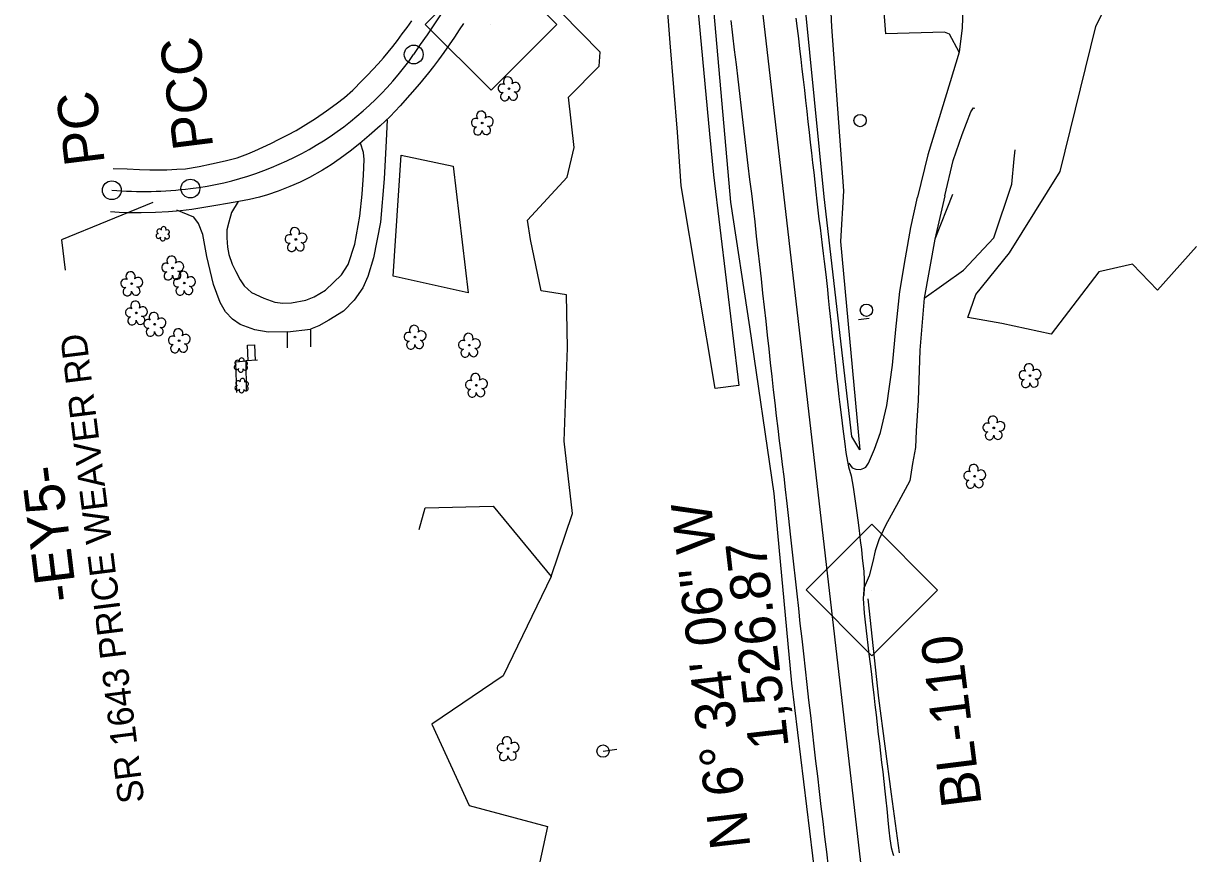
# Model space of a CAD drawing. Extents: x 476627 to 479509, y 495837 to 499842.
# Drawn here: x 477859.6 to 478327.6, y 496914.6 to 497245.6 of the extents above; entities that cross this region are included whole.
import ezdxf

# ---------------------------------------------------------------- set-up
doc = ezdxf.new("R2010")
doc.units = 0
for name, color, linetype in [('CTL Secondary Horizontal and Vertical CELL', 7, 'Continuous'), ('CTL Secondary Horizontal and Vertical Text', 7, 'Continuous'), ('Exist Guardrail', 7, 'Continuous'), ('Exist Horizontal Alignment', 7, 'Continuous'), ('Exist Horizontal Alignment Direction Label', 7, 'Continuous'), ('Exist Other Culture Area Outline', 7, 'Continuous'), ('Exist Other Culture Sign', 7, 'Continuous'), ('Exist Roads EOP', 7, 'Continuous'), ('Exist Roads EOP Leader', 7, 'Continuous'), ('Exist Roads EOP Other', 7, 'Continuous'), ('Exist Roads EOP Text', 7, 'Continuous'), ('Exist Roads Soil', 7, 'Continuous'), ('Exist Utilities Other Pole CELL', 7, 'Continuous'), ('Exist Utilities Power Pole CELL', 7, 'Continuous'), ('Exist Vegetation Hedge Row', 7, 'Continuous'), ('Exist Vegetation Shrub CELL', 7, 'Continuous'), ('Exist Vegetation Tree CELL', 7, 'Continuous'), ('Exist Vegetation Woods Line', 7, 'Continuous')]:
    doc.layers.add(name, color=color, linetype=linetype)

msp = doc.modelspace()

# ---------------------------------------------------------------- linework, layer by layer
at = {"layer": 'CTL Secondary Horizontal and Vertical CELL'}
for p, q in [((478046.04, 497245.12), (478046.04, 497245.12)), ((478197.94, 497019.66), (478197.94, 497019.66))]:
    msp.add_line(p, q, dxfattribs=at)
for points in [[(478019.96, 497245.21), (478046.17, 497271.41), (478072.42, 497245.16), (478046.21, 497218.96)], [(478171.87, 497019.75), (478198.07, 497045.96), (478224.32, 497019.7), (478198.12, 496993.5)]]:
    msp.add_lwpolyline(points, close=True, dxfattribs=at)
at = {"layer": 'Exist Guardrail'}
msp.add_lwpolyline([(478196.51, 497016.23), (478200.72, 496976.63), (478205.75, 496938.31), (478209.04, 496914.92)], dxfattribs=at)
at = {"layer": 'Exist Horizontal Alignment'}
msp.add_line((478241.22, 496498.17), (478119.71, 497553.37), dxfattribs=at)
for centre in [(478015.32, 497233.23), (477894.89, 497179.1), (477926.23, 497179.77)]:
    msp.add_circle(centre, 3.75, dxfattribs=at)
for centre, radius, start, end in [((477193.06, 497809.1), 1003.86, 324.99436, 333.75894), ((477910.8, 497306.43), 127.59, 276.944, 324.9944), ((477907.25, 497335.63), 157.01, 265.4855, 276.944)]:
    msp.add_arc(centre, radius, start, end, dxfattribs=at)
at = {"layer": 'Exist Other Culture Area Outline'}
msp.add_line((477944.56, 497110.62), (477948.31, 497111.05), dxfattribs=at)
for points in [[(477965.02, 497116.32), (477964.93, 497122.58), (477974.09, 497123.73), (477974.12, 497116.68)], [(477949.32, 497111.1), (477949.07, 497117.32), (477951.81, 497117.4), (477952.11, 497111.24)], [(477944.77, 497098.47), (477944.41, 497110.43)], [(477952.99, 497111.28), (477948.31, 497111.05), (477948.54, 497099.08)]]:
    msp.add_lwpolyline(points, dxfattribs=at)
at = {"layer": 'Exist Other Culture Sign'}
msp.add_line((478197.08, 497127.9), (478192.79, 497127.43), dxfattribs=at)
at = {"layer": 'Exist Roads EOP'}
for points in [[(478035.23, 497245.64), (478033.52, 497243.02), (478031.58, 497240.11), (478029.48, 497237.05), (478027.33, 497234), (478025.21, 497231.08), (478023.21, 497228.41), (478021.29, 497225.96), (478017.62, 497221.51), (478013.84, 497217.13), (478009.92, 497212.8), (478005.91, 497208.5), (478001.95, 497204.74), (477997.62, 497200.92), (477993.83, 497197.76), (477990.02, 497194.74), (477986.02, 497191.78), (477982.41, 497189.27), (477978.98, 497187.06), (477973.75, 497184.13), (477970.07, 497182.34), (477965.93, 497180.53), (477961.26, 497178.77), (477956.98, 497177.28), (477953.76, 497176.28), (477949.79, 497175.4), (477945.54, 497174.58), (477941.05, 497173.77), (477936.39, 497172.96), (477931.62, 497172.16), (477926.85, 497171.47), (477922.23, 497170.93), (477917.5, 497170.5), (477912.35, 497170.25), (477906.55, 497170.12), (477900.71, 497170.14), (477897.87, 497170.26), (477894.37, 497170.45)], [(477895.41, 497187.76), (477901.06, 497187.58), (477905.9, 497187.4), (477910.04, 497187.25), (477914.56, 497187.23), (477916.83, 497187.29), (477920.82, 497187.44), (477924.23, 497187.69), (477929.69, 497188.59), (477934.63, 497189.6), (477940.1, 497190.77), (477944.94, 497192.07), (477949.09, 497193.64), (477951.93, 497194.83), (477955.14, 497196.25), (477958.39, 497197.78), (477961.71, 497199.43), (477965.14, 497201.2), (477968.41, 497202.96), (477971.29, 497204.61), (477976.2, 497207.7), (477980.57, 497210.73), (477984.35, 497213.49), (477987.66, 497216.06), (477991.07, 497219.04), (477994.8, 497222.81), (477996.85, 497224.96), (477999, 497227.24), (478001.16, 497229.56), (478003.21, 497231.86), (478006.98, 497236.47), (478008.81, 497238.87), (478010.74, 497241.4), (478012.69, 497244.02), (478014.57, 497246.71)], [(478180.78, 496909.15), (478180.07, 496915.25), (478179.35, 496921.32), (478178.62, 496927.36), (478177.9, 496933.39), (478177.18, 496939.41), (478176.48, 496945.43), (478175.79, 496951.44), (478175.1, 496957.47), (478174.41, 496963.55), (478173.71, 496969.66), (478173.01, 496975.82), (478172.31, 496981.97), (478171.62, 496988.1), (478170.93, 496994.2), (478170.24, 497000.26), (478169.56, 497006.29), (478168.9, 497012.27), (478168.25, 497018.21), (478167.62, 497024.1), (478166.99, 497030), (478166.34, 497035.98), (478165.68, 497042.03), (478164.99, 497048.16), (478164.32, 497054.13), (478163.67, 497059.72), (478163.06, 497064.92), (478162.47, 497069.73), (478161.9, 497074.41), (478161.31, 497079.21), (478160.71, 497084.14), (478160.1, 497089.18), (478159.48, 497094.33), (478158.88, 497099.57), (478158.27, 497104.89), (478157.68, 497110.31), (478157.08, 497115.8), (478156.48, 497121.32), (478155.87, 497126.88), (478155.25, 497132.48), (478154.63, 497138.12), (478154.01, 497143.77), (478153.39, 497149.44), (478152.77, 497155.13), (478152.14, 497160.82), (478151.49, 497166.49), (478150.83, 497172.13), (478150.16, 497177.75), (478149.48, 497183.37), (478148.8, 497189.01), (478148.13, 497194.68), (478147.46, 497200.37), (478146.78, 497206.08), (478146.11, 497211.83), (478145.42, 497217.61), (478144.73, 497223.41), (478144.04, 497229.25), (478143.35, 497235.1), (478142.67, 497240.96), (478141.99, 497246.84)], [(478167.81, 497247.69), (478168.29, 497243.63), (478168.77, 497239.56), (478169.25, 497235.49), (478169.73, 497231.42), (478170.21, 497227.33), (478170.68, 497223.2), (478171.16, 497219.03), (478171.64, 497214.83), (478172.11, 497210.61), (478172.59, 497206.43), (478173.06, 497202.27), (478173.53, 497198.14), (478174, 497194.07), (478174.45, 497190.06), (478174.9, 497186.14), (478175.33, 497182.29), (478175.76, 497178.51), (478176.18, 497174.79), (478176.59, 497171.15), (478177, 497167.58), (478177.41, 497164.06), (478177.81, 497160.61), (478178.22, 497157.22), (478178.64, 497153.89), (478179.03, 497150.75), (478179.69, 497145.44), (478180.38, 497139.5), (478180.72, 497136.18), (478181.11, 497132.23), (478181.69, 497126.55), (478182.27, 497120.93), (478182.86, 497115.31), (478183.15, 497112.68), (478183.54, 497109.26), (478184.03, 497105.05), (478184.53, 497100.71), (478184.97, 497096.91), (478185.35, 497093.64), (478185.96, 497088.51), (478186.49, 497084.01), (478186.75, 497081.91), (478187.25, 497078.03), (478187.74, 497074.55), (478188.79, 497068.84), (478189.78, 497065.24), (478190.68, 497060.69), (478191.49, 497055.11), (478191.97, 497051.45), (478192.48, 497047.49), (478192.99, 497043.43), (478193.48, 497039.5), (478193.92, 497035.81), (478194.29, 497032.47), (478194.84, 497027.03), (478195.09, 497023.7), (478195.09, 497021.63), (478194.65, 497016.28), (478195.04, 497010.48), (478195.43, 497006.88), (478196.1, 497001.22), (478196.51, 496997.77), (478196.95, 496994.1), (478197.41, 496990.22), (478197.9, 496986.12), (478198.39, 496981.96), (478198.86, 496977.88), (478199.33, 496973.88), (478199.78, 496969.96), (478200.22, 496966.1), (478200.67, 496962.28), (478201.11, 496958.48), (478201.56, 496954.71), (478202, 496950.95), (478202.43, 496947.17), (478202.85, 496943.37), (478203.27, 496939.54), (478203.66, 496935.85), (478204.02, 496932.44), (478204.66, 496926.48), (478204.92, 496924.01), (478205.32, 496920.44), (478205.85, 496916.99), (478206.46, 496914.68), (478206.77, 496913.89)]]:
    msp.add_lwpolyline(points, dxfattribs=at)
at = {"layer": 'Exist Roads EOP Leader'}
msp.add_lwpolyline([(477911.24, 497174.19), (477874.76, 497159.27), (477876.27, 497147.26)], dxfattribs=at)
at = {"layer": 'Exist Roads EOP Other'}
for points in [[(478234.58, 497255.76), (478234.09, 497243.91), (478232.9, 497234.19), (478229.32, 497222.36), (478224.43, 497206.22), (478220.47, 497193.22), (478216.26, 497176.28)], [(478227.18, 497176.89), (478230.49, 497190.94), (478234.13, 497201.38), (478237.6, 497210.3), (478238.69, 497211.92), (478239.15, 497211.85)], [(478188.86, 497070.34), (478190.3, 497068.4), (478191.74, 497067.91), (478193.58, 497067.8), (478194.87, 497068.33), (478195.63, 497068.74), (478196.75, 497070.24), (478199.13, 497075.89), (478201.53, 497082.51), (478204.12, 497093.25), (478206.39, 497109.37), (478207.68, 497123.62), (478209.32, 497138.79), (478211.55, 497152.2), (478213.68, 497164.25), (478216.26, 497176.28)], [(478227.18, 497176.89), (478223.23, 497159.59), (478218.95, 497136.12), (478217.23, 497115.29), (478216.54, 497095.28), (478215.82, 497083.22), (478215.49, 497076.53), (478214.32, 497070.17), (478213.3, 497063.29), (478208.75, 497054.86), (478203.56, 497045.36), (478200.94, 497039.69), (478199.44, 497035.36), (478198.53, 497031.09), (478196.97, 497025.37), (478194.98, 497020.7), (478194.83, 497017.55)]]:
    msp.add_lwpolyline(points, dxfattribs=at)
at = {"layer": 'Exist Roads Soil'}
for points in [[(478232.9, 497234.19), (478229.08, 497241.38), (478227.08, 497242.13), (478203.69, 497241.5), (478202.19, 497260.65), (478201.46, 497277.13), (478202.27, 497279.15), (478209.18, 497280.95), (478211.76, 497282.22), (478214.52, 497285.39)], [(478004.71, 497207.12), (478004.35, 497198.84), (478003.51, 497183.67), (478002.14, 497166.34), (477999.29, 497152.11), (477997.02, 497144.74), (477995.02, 497140.13), (477991.61, 497135.24), (477987.33, 497130.92), (477981.46, 497127.24), (477977.53, 497125.03), (477974.09, 497123.73)], [(477945.27, 497174.56), (477942.68, 497170.16), (477941.54, 497166.42), (477940.81, 497163.32), (477940.75, 497160.15), (477941.04, 497156.46), (477941.53, 497153.51), (477942.85, 497149.68), (477944.3, 497146.72), (477946.06, 497143.35), (477947.71, 497141.01), (477950.56, 497138.38), (477955.52, 497136.01), (477959.97, 497134.48), (477963.16, 497134.04), (477966.63, 497134.25), (477972.23, 497135.26), (477975.67, 497136.58), (477980.1, 497139.29), (477986.52, 497145.4), (477989.14, 497149.51), (477991.9, 497157.65), (477993.79, 497168.7), (477994.81, 497177.54), (477995.32, 497185.1), (477995.51, 497191.42), (477995.23, 497194.09), (477994.09, 497197.93)], [(478218.95, 497136.12), (478234.59, 497147.19), (478246.82, 497160.07), (478253.98, 497181.47), (478254.93, 497191.6), (478255.23, 497195.18)], [(478230.22, 497177.39), (478223.23, 497159.59)], [(477964.93, 497122.58), (477957.24, 497122.47), (477951.92, 497123.44), (477946.12, 497125.54), (477942.97, 497127.71), (477940.2, 497130.65), (477938.14, 497134.34), (477935.52, 497141.52), (477932.84, 497152.72), (477931.21, 497161.46), (477929.45, 497165.82), (477927.64, 497168.34), (477920.89, 497171.21)]]:
    msp.add_lwpolyline(points, dxfattribs=at)
at = {"layer": 'Exist Utilities Other Pole CELL'}
for centre in [(478193.42, 497206.9), (478195.91, 497131.26)]:
    msp.add_circle(centre, 2.46, dxfattribs=at)
at = {"layer": 'Exist Utilities Power Pole CELL'}
for q in [(478096.41, 496956.24), (478090.84, 496955.47)]:
    msp.add_line((478090.84, 496955.47), q, dxfattribs=at)
msp.add_circle((478090.84, 496955.47), 2.45, dxfattribs=at)
at = {"layer": 'Exist Vegetation Hedge Row'}
for points in [[(478190.09, 497080.94), (478179.04, 497176.49), (478167.62, 497291.69), (478149.68, 497459.52), (478153.94, 497461.52), (478164.92, 497407.53), (478169.64, 497380.94), (478176.79, 497323.8), (478179.27, 497301.23), (478182, 497244.2), (478186.73, 497178.82), (478185.59, 497158.67), (478193.35, 497075.53), (478190.09, 497080.94)], [(478061.9, 497159.5), (478060.76, 497167.21), (478076.59, 497184.26), (478079.28, 497196.19), (478077.12, 497216.22), (478089.28, 497228.61), (478089.68, 497234.1), (478074.26, 497249.81), (478051.02, 497260.79), (478081, 497317.4), (478090.81, 497331.53), (478107.74, 497357.73), (478122.56, 497359.77), (478132.29, 497281.51), (478141.65, 497174.35)], [(478141.65, 497174.35), (478149.25, 497124.62), (478158.96, 497058.2), (478166.01, 496982.58), (478178.06, 496884.14), (478154.97, 496858.56), (478116.58, 496816.35), (478093.34, 496801.61), (478073.88, 496796.87), (478056.27, 496795.04), (478052.86, 496799.11), (478045.86, 496797.88)], [(478070.12, 497025.14), (478078.66, 497050.24), (478075.36, 497079.1), (478076.69, 497116.32), (478076.31, 497137.46), (478066.2, 497139.04), (478061.9, 497159.5)]]:
    msp.add_lwpolyline(points, dxfattribs=at)
at = {"layer": 'Exist Vegetation Shrub CELL'}
for p, q in [((477915.3, 497161.55), (477915.3, 497161.55)), ((477946.44, 497109.19), (477946.44, 497109.19)), ((477946.77, 497101.02), (477946.77, 497101.02))]:
    msp.add_line(p, q, dxfattribs=at)
for centre, radius, start, end in [((477915.53, 497163.59), 0.99, 334.8391, 200.4717), ((477913.5, 497160.85), 0.955, 95.1099, 327.9534), ((477913.82, 497162.68), 0.968, 35.8908, 245.4216), ((477915.18, 497159.87), 0.984, 151.2797, 21.387), ((477916.94, 497160.62), 0.937, 204.9913, 73.4601), ((477916.98, 497162.42), 0.929, 284.4567, 126.0861), ((477944.64, 497108.49), 0.955, 95.1099, 327.9534), ((477944.96, 497110.32), 0.968, 35.8908, 245.4216), ((477946.31, 497107.51), 0.984, 151.2797, 21.387), ((477946.67, 497111.23), 0.99, 334.8391, 200.4717), ((477948.08, 497108.27), 0.937, 204.9913, 73.4601), ((477948.11, 497110.06), 0.929, 284.4567, 126.0861), ((477945.29, 497102.14), 0.968, 35.8908, 245.4216), ((477947, 497103.06), 0.99, 334.8391, 200.4717), ((477944.97, 497100.31), 0.955, 95.1099, 327.9534), ((477946.64, 497099.33), 0.984, 151.2797, 21.387), ((477948.41, 497100.09), 0.937, 204.9913, 73.4601), ((477948.44, 497101.88), 0.929, 284.4567, 126.0861)]:
    msp.add_arc(centre, radius, start, end, dxfattribs=at)
at = {"layer": 'Exist Vegetation Tree CELL'}
for p, q in [((478053.33, 497219.58), (478053.33, 497219.58)), ((478042.64, 497205.91), (478042.64, 497205.91)), ((477968.33, 497159.49), (477968.33, 497159.49)), ((477919.12, 497148.13), (477919.12, 497148.13)), ((477902.79, 497141.84), (477902.79, 497141.84)), ((477923.82, 497142.08), (477923.82, 497142.08)), ((477904.67, 497130.19), (477904.67, 497130.19)), ((477912.01, 497125.67), (477912.01, 497125.67)), ((477921.75, 497119.12), (477921.75, 497119.12)), ((478015.85, 497120.53), (478015.85, 497120.53)), ((478037.53, 497117.33), (478037.53, 497117.33)), ((478261.15, 497105.21), (478261.15, 497105.21)), ((478040.32, 497101.36), (478040.32, 497101.36)), ((478246.73, 497084.35), (478246.73, 497084.35)), ((478239.11, 497065.08), (478239.11, 497065.08)), ((478052.91, 496956.48), (478052.91, 496956.48))]:
    msp.add_line(p, q, dxfattribs=at)
for centre in [(478053.33, 497219.58), (478042.64, 497205.91), (477968.33, 497159.49), (477919.12, 497148.13), (477902.79, 497141.84), (477923.82, 497142.08), (477904.67, 497130.19), (477912.01, 497125.67), (477921.75, 497119.12), (478015.85, 497120.53), (478037.53, 497117.33), (478261.15, 497105.21), (478040.32, 497101.36), (478246.73, 497084.35), (478239.11, 497065.08), (478052.91, 496956.48)]:
    msp.add_circle(centre, 0.326, dxfattribs=at)
for centre, radius, start, end in [((478050.72, 497219.73), 1.73, 62.6636, 279.3457), ((478052.94, 497222.45), 1.86, 330.1651, 219.7134), ((478055.87, 497220.17), 1.9, 257.1011, 134.1999), ((478051.62, 497216.46), 1.69, 111.5671, 6.231), ((478055, 497216.68), 1.7, 181.2822, 74.56), ((478042.25, 497208.78), 1.86, 330.1651, 219.7134), ((478040.03, 497206.06), 1.73, 62.6636, 279.3457), ((478045.19, 497206.5), 1.9, 257.1011, 134.1999), ((478040.93, 497202.79), 1.69, 111.5671, 6.231), ((478044.31, 497203.01), 1.7, 181.2822, 74.56), ((477967.94, 497162.37), 1.86, 330.1651, 219.7134), ((477965.72, 497159.65), 1.73, 62.6636, 279.3457), ((477970.88, 497160.08), 1.9, 257.1011, 134.1999), ((477966.62, 497156.37), 1.69, 111.5671, 6.231), ((477970, 497156.59), 1.7, 181.2822, 74.56), ((477916.51, 497148.28), 1.73, 62.6636, 279.3457), ((477918.73, 497151), 1.86, 330.1651, 219.7134), ((477921.67, 497148.71), 1.9, 257.1011, 134.1999), ((477902.4, 497144.71), 1.86, 330.1651, 219.7134), ((477917.41, 497145.01), 1.69, 111.5671, 6.231), ((477920.79, 497145.23), 1.7, 181.2822, 74.56), ((477923.44, 497144.95), 1.86, 330.1651, 219.7134), ((477900.18, 497141.99), 1.73, 62.6636, 279.3457), ((477904.46, 497138.94), 1.7, 181.2822, 74.56), ((477905.33, 497142.43), 1.9, 257.1011, 134.1999), ((477921.22, 497142.23), 1.73, 62.6636, 279.3457), ((477922.12, 497138.96), 1.69, 111.5671, 6.231), ((477925.49, 497139.18), 1.7, 181.2822, 74.56), ((477926.37, 497142.67), 1.9, 257.1011, 134.1999), ((477901.08, 497138.72), 1.69, 111.5671, 6.231), ((477902.06, 497130.34), 1.73, 62.6636, 279.3457), ((477904.28, 497133.06), 1.86, 330.1651, 219.7134), ((477907.22, 497130.78), 1.9, 257.1011, 134.1999), ((477902.96, 497127.07), 1.69, 111.5671, 6.231), ((477906.34, 497127.29), 1.7, 181.2822, 74.56), ((477909.4, 497125.82), 1.73, 62.6636, 279.3457), ((477911.62, 497128.54), 1.86, 330.1651, 219.7134), ((477914.56, 497126.26), 1.9, 257.1011, 134.1999), ((477910.3, 497122.55), 1.69, 111.5671, 6.231), ((477913.68, 497122.77), 1.7, 181.2822, 74.56), ((477921.37, 497121.99), 1.86, 330.1651, 219.7134), ((478013.25, 497120.69), 1.73, 62.6636, 279.3457), ((478015.47, 497123.41), 1.86, 330.1651, 219.7134), ((478018.4, 497121.12), 1.9, 257.1011, 134.1999), ((478037.14, 497120.2), 1.86, 330.1651, 219.7134), ((477919.15, 497119.27), 1.73, 62.6636, 279.3457), ((477920.05, 497115.99), 1.69, 111.5671, 6.231), ((477923.42, 497116.22), 1.7, 181.2822, 74.56), ((477924.3, 497119.7), 1.9, 257.1011, 134.1999), ((478014.15, 497117.41), 1.69, 111.5671, 6.231), ((478017.53, 497117.64), 1.7, 181.2822, 74.56), ((478034.92, 497117.48), 1.73, 62.6636, 279.3457), ((478040.07, 497117.92), 1.9, 257.1011, 134.1999), ((478035.82, 497114.21), 1.69, 111.5671, 6.231), ((478039.2, 497114.43), 1.7, 181.2822, 74.56), ((478260.76, 497108.08), 1.86, 330.1651, 219.7134), ((478263.69, 497105.79), 1.9, 257.1011, 134.1999), ((478037.71, 497101.52), 1.73, 62.6636, 279.3457), ((478039.93, 497104.24), 1.86, 330.1651, 219.7134), ((478042.87, 497101.95), 1.9, 257.1011, 134.1999), ((478258.54, 497105.36), 1.73, 62.6636, 279.3457), ((478259.44, 497102.09), 1.69, 111.5671, 6.231), ((478262.82, 497102.31), 1.7, 181.2822, 74.56), ((478038.62, 497098.24), 1.69, 111.5671, 6.231), ((478041.99, 497098.47), 1.7, 181.2822, 74.56), ((478246.35, 497087.22), 1.86, 330.1651, 219.7134), ((478244.13, 497084.5), 1.73, 62.6636, 279.3457), ((478249.28, 497084.94), 1.9, 257.1011, 134.1999), ((478245.03, 497081.23), 1.69, 111.5671, 6.231), ((478248.41, 497081.45), 1.7, 181.2822, 74.56), ((478236.5, 497065.23), 1.73, 62.6636, 279.3457), ((478238.72, 497067.95), 1.86, 330.1651, 219.7134), ((478241.66, 497065.66), 1.9, 257.1011, 134.1999), ((478237.41, 497061.95), 1.69, 111.5671, 6.231), ((478240.78, 497062.18), 1.7, 181.2822, 74.56), ((478050.31, 496956.63), 1.73, 62.6636, 279.3457), ((478052.53, 496959.35), 1.86, 330.1651, 219.7134), ((478055.46, 496957.07), 1.9, 257.1011, 134.1999), ((478051.21, 496953.36), 1.69, 111.5671, 6.231), ((478054.59, 496953.58), 1.7, 181.2822, 74.56)]:
    msp.add_arc(centre, radius, start, end, dxfattribs=at)
at = {"layer": 'Exist Vegetation Woods Line'}
for points in [[(478121.98, 497180.8), (478120.53, 497202.22), (478117.63, 497237.89), (478114.13, 497282.93), (478112.24, 497301.41), (478117.88, 497316.42), (478123.49, 497307.06), (478133.32, 497201.56), (478134.86, 497185.26)], [(478273.28, 497186.57), (478287.42, 497244.42), (478297.46, 497264.61), (478306.34, 497279.2), (478312.52, 497280.03)], [(478037, 497138.2), (478007.1, 497144.83), (478010.26, 497193.1), (478031.12, 497188.67), (478037, 497138.2)], [(478134.86, 497185.26), (478144.98, 497101.27), (478135.65, 497100.07), (478121.98, 497180.8)], [(478327.62, 497156.61), (478311.98, 497139.3), (478302.03, 497149.63), (478288.6, 497146.54), (478269.66, 497121.73), (478249.98, 497125.92), (478236.38, 497128.35), (478239.52, 497137.47), (478252.96, 497154.16), (478273.28, 497186.57)], [(478017.5, 497043.87), (478019.87, 497052.41), (478047.06, 497053.13), (478070.12, 497025.14), (478051.01, 496985.43), (478022.6, 496966.25), (478037.42, 496933.81), (478068.72, 496925.36), (478058.71, 496879.36), (478038.1, 496865.2)]]:
    msp.add_lwpolyline(points, dxfattribs=at)

# ---------------------------------------------------------------- texts
at = {"layer": 'CTL Secondary Horizontal and Vertical Text'}
msp.add_text('BL-110', height=16, rotation=97.1248, dxfattribs=at).set_placement((478241.96, 496934.2))
at = {"layer": 'Exist Horizontal Alignment'}
for s, p in [('PCC', (477935.42, 497196.26)), ('PC', (477892.16, 497189.94))]:
    msp.add_text(s, height=16, rotation=97.1247, dxfattribs=at).set_placement(p)
at = {"layer": 'Exist Horizontal Alignment Direction Label'}
for s, rotation, p in [('-EY5-', 96.9446, (477881.07, 497015.81)), ('N 6%%d 34\' 06" W', 96.5685, (478149.71, 496917.22)), ('1,526.87', 96.5685, (478165, 496957.19))]:
    msp.add_text(s, height=16, rotation=rotation, dxfattribs=at).set_placement(p)
at = {"layer": 'Exist Roads EOP Text'}
msp.add_text('SR 1643 PRICE WEAVER RD', height=10.4, rotation=97.1247, dxfattribs=at).set_placement((477907.92, 496935.33))

doc.saveas('drawing.dxf')
